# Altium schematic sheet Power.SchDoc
size A4
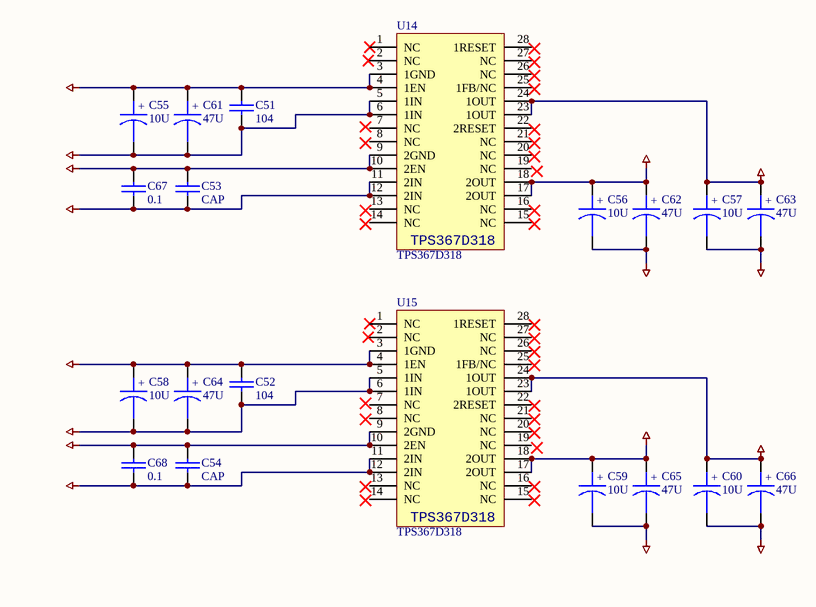
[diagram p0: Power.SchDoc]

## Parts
C51  104  [CC2012-0805]
C52  104  [CC2012-0805]
C53  CAP  [CC2012-0805]
C54  CAP  [CC2012-0805]
C55  10U  [RB5-10.5]
C56  10U  [RB5-10.5]
C57  10U  [RB5-10.5]
C58  10U  [RB5-10.5]
C59  10U  [RB5-10.5]
C60  10U  [RB5-10.5]
C61  47U  [RB5-10.5]
C62  47U  [RB5-10.5]
C63  47U  [RB5-10.5]
C64  47U  [RB5-10.5]
C65  47U  [RB5-10.5]
C66  47U  [RB5-10.5]
C67  0.1  [CC2012-0805]
C68  0.1  [CC2012-0805]
U14  TPS367D318  [TSSO10X6-G28]
U15  TPS367D318  [TSSO10X6-G28]

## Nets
1.8V: C57.1 C60.1 C63.1 C66.1 U14.23(1OUT) U14.24(1OUT) U15.23(1OUT) U15.24(1OUT)
3.3V: C56.1 C59.1 C62.1 C65.1 U14.17(2OUT) U14.18(2OUT) U15.17(2OUT) U15.18(2OUT)
5V: C51.2 C52.2 C53.1 C54.1 C55.2 C58.2 C61.2 C64.2 C67.2 C68.2 U14.5(1IN) U14.6(1IN) U14.11(2IN) U14.12(2IN) U15.5(1IN) U15.6(1IN) U15.11(2IN) U15.12(2IN)
DGND: C51.1 C52.1 C53.2 C54.2 C55.1 C56.2 C57.2 C58.1 C59.2 C60.2 C61.1 C62.2 C63.2 C64.1 C65.2 C66.2 C67.1 C68.1 U14.3(1GND) U14.4(1EN) U14.9(2GND) U14.10(2EN) U15.3(1GND) U15.4(1EN) U15.9(2GND) U15.10(2EN)

Not connected (* = marked no-connect by the designer): U14 1(NC)* 2(NC) 7(NC) 8(NC) 13(NC) 14(NC) 15(NC) 16(NC) 19(NC) 20(NC) 21(NC) 22(2RESET) 25(1FB/NC) 26(NC) 27(NC) 28(1RESET); U15 1(NC)* 2(NC) 7(NC) 8(NC) 13(NC) 14(NC) 15(NC) 16(NC) 19(NC) 20(NC) 21(NC) 22(2RESET) 25(1FB/NC) 26(NC) 27(NC) 28(1RESET)

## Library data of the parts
C51-C54 C67 C68 = CAP: Capacitor
C55-C66 = CAPACITOR POL: Capacitor
U14 U15 = TPS367D318: POWRE; Manufacturer: Texas Instruments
